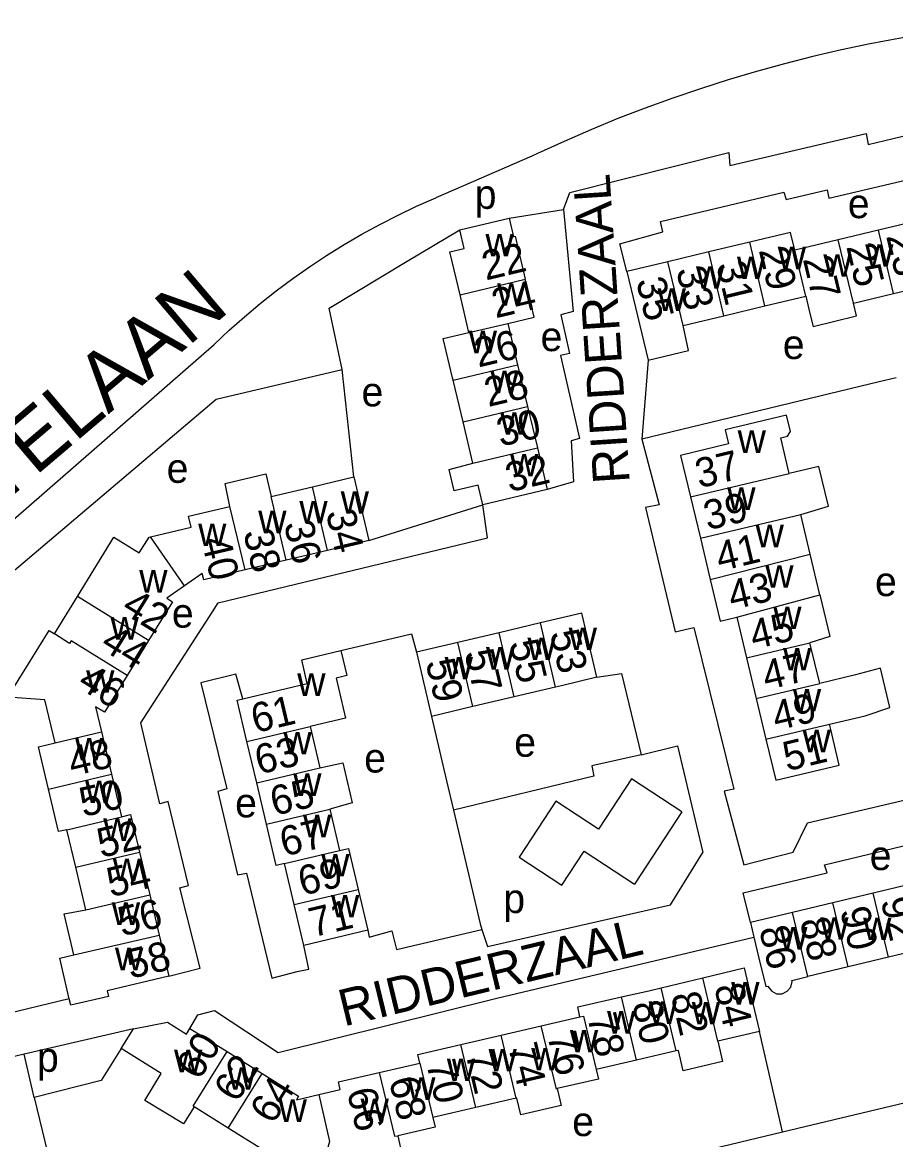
# Model space of a CAD drawing. Extents: x 157646 to 159241, y 379213 to 381217.
# Drawn here: x 158360.1 to 158479.3, y 380979.6 to 381132.2 of the extents above; entities that cross this region are included whole.
import ezdxf

# ---------------------------------------------------------------- set-up
doc = ezdxf.new("R2010")
doc.units = 0
for name, color, linetype in [('BLT_Basislijn', 7, 'Continuous'), ('BLT_Bebouwing', 7, 'Continuous'), ('BLT_Centroide', 7, 'Continuous'), ('BLT_Huisnummer', 7, 'Continuous'), ('BLT_Huisnummer_ tussenligend', 7, 'Continuous'), ('BLT_Onderverdeling_panden', 7, 'Continuous'), ('BLT_Straatnaam', 7, 'Continuous'), ('BLT_Straatnaam_hoofdweg', 7, 'Continuous')]:
    doc.layers.add(name, color=color, linetype=linetype)

msp = doc.modelspace()

# ---------------------------------------------------------------- linework, layer by layer
at = {"layer": 'BLT_Basislijn'}
for p, q in [((158429.63, 381113.93), (158416.55, 381108.25)), ((158352.16, 381058.47), (158386.26, 381088.22)), ((158445.52, 381086.08), (158444.65, 381075.27)), ((158405.32, 381070.12), (158403.73, 381084.79)), ((158477.05, 381083.1), (158444.65, 381075.27)), ((158479.4, 381083.66), (158477.05, 381083.1)), ((158407.38, 381061.43), (158422.93, 381066.31)), ((158415.95, 381037.42), (158418, 381028.6)), ((158418, 381028.6), (158418.93, 381024.62)), ((158443.27, 381028.88), (158438.76, 381022.01)), ((158450.14, 381024.37), (158443.27, 381028.88)), ((158432.92, 381025.85), (158427.89, 381018.19)), ((158438.76, 381022.01), (158432.92, 381025.85)), ((158418.93, 381024.62), (158422.56, 381009.1)), ((158450.14, 381024.37), (158443.66, 381014.5)), ((158433.74, 381014.35), (158436.79, 381019.01)), ((158436.79, 381019.01), (158443.66, 381014.5)), ((158427.89, 381018.19), (158433.74, 381014.35)), ((158422.56, 381009.1), (158422.81, 381008.33)), ((158424.88, 380998.94), (158459.96, 381007.29)), ((158366.47, 380998.84), (158355.18, 380996.12)), ((158375.23, 380994.76), (158360.32, 380991.27)), ((158463.89, 380980.68), (158460.71, 380994.38)), ((158463.89, 380980.68), (158511.15, 380991.95)), ((158360.32, 380991.27), (158351.84, 380989.29)), ((158361.67, 380985.35), (158360.32, 380991.27)), ((158418.22, 380969.78), (158463.89, 380980.68))]:
    msp.add_line(p, q, dxfattribs=at)
for points in [[(158495.56, 381132.22), (158491.59, 381131.78), (158487.63, 381131.27), (158483.68, 381130.68), (158479.74, 381130.02), (158475.82, 381129.27), (158471.91, 381128.44), (158468.02, 381127.54), (158464.15, 381126.56), (158460.3, 381125.5), (158456.47, 381124.36), (158452.66, 381123.15), (158448.88, 381121.86), (158445.13, 381120.5), (158441.4, 381119.06), (158437.71, 381117.55), (158434.04, 381115.96), (158430.41, 381114.3), (158429.63, 381113.93)], [(158433.98, 381106.64), (158434.82, 381108.99), (158456.55, 381114.43), (158456.67, 381112.68), (158475.29, 381117.04), (158475.59, 381115.54), (158485.82, 381118), (158484.86, 381122.23), (158495.46, 381124.81), (158496.3, 381121.35), (158503.33, 381123.36)], [(158442.63, 381098.18), (158441.67, 381101.95), (158447.51, 381103.59), (158447.19, 381105.03), (158464.06, 381109.04), (158464.35, 381108.01), (158469.95, 381109.35), (158470.21, 381108.19), (158480.86, 381110.72), (158480.68, 381111.49), (158492.02, 381114.24), (158492.32, 381112.97), (158498.99, 381114.49), (158499.82, 381110.23), (158498.96, 381110.26)], [(158386.26, 381088.22), (158388.3, 381090.15), (158390.39, 381092.01), (158392.54, 381093.81), (158394.74, 381095.55), (158396.98, 381097.23), (158399.27, 381098.84), (158401.61, 381100.39), (158403.99, 381101.87), (158406.41, 381103.28), (158408.87, 381104.62), (158411.37, 381105.89), (158413.9, 381107.09), (158416.55, 381108.25)], [(158426.53, 381105.47), (158433.98, 381106.64)], [(158433.98, 381106.64), (158435.27, 381092.73), (158433.61, 381092.25), (158434.78, 381086.99), (158433.57, 381086.7), (158436.16, 381075.36), (158434.99, 381075.07), (158435.31, 381069.47), (158431.73, 381068.4)], [(158403.73, 381084.79), (158401.98, 381093.18), (158412.6, 381099.61), (158419.79, 381103.88)], [(158346.67, 381046.99), (158386.52, 381080.76), (158403.73, 381084.79)], [(158444.65, 381075.27), (158447.01, 381066.3), (158445.18, 381065.93), (158449.2, 381048.97), (158451.75, 381049.54), (158457.24, 381027.49), (158455.91, 381027.23), (158458.57, 381017.13), (158465.31, 381018.9)], [(158382.77, 381014.34), (158379.96, 381025.82), (158378.84, 381025.49), (158376.22, 381036.56), (158386.05, 381051.68), (158386.8, 381052.92), (158423.59, 381061.81), (158422.93, 381066.31)], [(158403.56, 381046.4), (158413.19, 381048.68)], [(158413.19, 381048.68), (158413.87, 381046.18)], [(158438.53, 381042.77), (158441.86, 381043.28), (158444.57, 381032.17)], [(158390.15, 381039.84), (158389.23, 381043.18), (158384.44, 381042.01), (158387.97, 381027.53), (158386.77, 381027.16), (158389.44, 381015.77)], [(158444.57, 381032.17), (158449.51, 381033.41), (158452.97, 381018.84)], [(158444.57, 381032.17), (158437.82, 381030.67), (158438.09, 381029.27), (158418.93, 381024.62)], [(158465.31, 381018.9), (158467.28, 381022.88), (158492.26, 381028.74)], [(158459.49, 381009.28), (158458.48, 381013.34), (158469.96, 381016.06), (158469.6, 381017.14), (158492.15, 381022.55), (158492.37, 381021.36), (158503.42, 381023.91), (158504.71, 381018.63)], [(158422.81, 381008.33), (158423.59, 381005.98), (158448.59, 381011.68), (158452.97, 381018.84)], [(158389.44, 381015.77), (158390.66, 381016.02), (158394.12, 381001.66), (158397.6, 381002.57), (158399.19, 381002.91), (158398.51, 381006.15)], [(158380.07, 381001.96), (158384.33, 381003.02), (158381.55, 381013.99), (158382.77, 381014.34)], [(158407.22, 381008.21), (158407.43, 381007.29), (158410.51, 381008.13), (158411.15, 381005.59), (158422.81, 381008.33)], [(158382.95, 380994.79), (158384.04, 380996.64), (158386.3, 380997.24), (158395, 380991.53), (158424.88, 380998.94)], [(158373.55, 380992.07), (158370.81, 380987.7), (158361.67, 380985.35)], [(158361.67, 380985.35), (158363.86, 380976.35), (158369.39, 380964.25)]]:
    msp.add_lwpolyline(points, dxfattribs=at)
at = {"layer": 'BLT_Bebouwing'}
for p, q in [((158419.79, 381103.88), (158426.53, 381105.47)), ((158482.7, 381105.19), (158476.98, 381103.83)), ((158476.98, 381103.83), (158471.48, 381102.52)), ((158459.39, 381102.18), (158453.8, 381100.85)), ((158471.48, 381102.52), (158465.55, 381101.1)), ((158453.8, 381100.85), (158448.21, 381099.52)), ((158448.21, 381099.52), (158442.63, 381098.18)), ((158442.63, 381098.18), (158445.52, 381086.08)), ((158473.55, 381093.88), (158479.05, 381095.2)), ((158421.05, 381089.85), (158419.83, 381095.02)), ((158461.47, 381093.49), (158467.05, 381094.82)), ((158450.29, 381090.82), (158455.88, 381092.15)), ((158455.88, 381092.15), (158461.47, 381093.49)), ((158426.36, 381091.1), (158427.7, 381085.43)), ((158427.7, 381085.43), (158429.05, 381079.75)), ((158420.24, 381077.67), (158418.9, 381083.34)), ((158429.05, 381079.75), (158430.39, 381074.08)), ((158421.59, 381071.99), (158420.24, 381077.67)), ((158430.39, 381074.08), (158431.73, 381068.4)), ((158399.68, 381068.78), (158405.32, 381070.12)), ((158405.32, 381070.12), (158407.38, 381061.43)), ((158394.05, 381067.45), (158399.68, 381068.78)), ((158431.73, 381068.4), (158422.93, 381066.31)), ((158451.3, 381067.41), (158452.65, 381061.76)), ((158467.67, 381059.56), (158466.38, 381064.99)), ((158377.57, 381061.94), (158383.13, 381063.26)), ((158452.65, 381061.76), (158454, 381056.1)), ((158401.74, 381060.09), (158396.11, 381058.76)), ((158407.38, 381061.43), (158401.74, 381060.09)), ((158396.11, 381058.76), (158390.47, 381057.42)), ((158468.99, 381054.03), (158467.67, 381059.56)), ((158384.63, 381056.95), (158382.2, 381055.26)), ((158382.2, 381055.26), (158379.78, 381053.58)), ((158364.45, 381048.72), (158367.57, 381053.78)), ((158457.62, 381050.99), (158458.95, 381045.42)), ((158430.81, 381050.19), (158425.17, 381048.85)), ((158425.17, 381048.85), (158419.52, 381047.51)), ((158377.31, 381047.78), (158374.37, 381043.02)), ((158419.52, 381047.51), (158413.87, 381046.18)), ((158468.95, 381041.92), (158467.62, 381047.49)), ((158458.95, 381045.42), (158460.28, 381039.86)), ((158374.37, 381043.02), (158371.27, 381037.98)), ((158432.89, 381041.43), (158427.24, 381040.09)), ((158371.27, 381037.98), (158370.07, 381038.72)), ((158370.07, 381038.72), (158370.88, 381035.31)), ((158389.39, 381039.66), (158390.15, 381039.84)), ((158390.73, 381034.01), (158389.39, 381039.66)), ((158421.59, 381038.75), (158415.95, 381037.42)), ((158427.24, 381040.09), (158421.59, 381038.75)), ((158460.28, 381039.86), (158461.61, 381034.29)), ((158399.36, 381036.05), (158400.7, 381030.4)), ((158370.88, 381035.31), (158372.25, 381029.52)), ((158461.61, 381034.29), (158462.94, 381028.72)), ((158392.07, 381028.36), (158390.73, 381034.01)), ((158372.25, 381029.52), (158373.62, 381023.72)), ((158462.94, 381028.72), (158471.61, 381030.78)), ((158393.41, 381022.71), (158392.07, 381028.36)), ((158402.04, 381024.75), (158403.38, 381019.1)), ((158367.36, 381016.82), (158366.15, 381021.95)), ((158376.06, 381018.89), (158377.45, 381013.04)), ((158397.19, 381011.73), (158395.87, 381017.32)), ((158368.74, 381010.98), (158367.36, 381016.82)), ((158481.75, 381014.6), (158476.26, 381013.29)), ((158377.45, 381013.04), (158378.74, 381007.56)), ((158405.9, 381013.8), (158407.22, 381008.21)), ((158476.26, 381013.29), (158470.74, 381011.97)), ((158398.51, 381006.15), (158397.19, 381011.73)), ((158470.74, 381011.97), (158465.23, 381010.65)), ((158465.23, 381010.65), (158459.49, 381009.28)), ((158407.22, 381008.21), (158398.51, 381006.15)), ((158459.49, 381009.28), (158459.96, 381007.29)), ((158378.74, 381007.56), (158380.07, 381001.96)), ((158453, 381001.72), (158458.64, 381003.07)), ((158472.84, 381003.2), (158467.33, 381001.89)), ((158447.32, 381000.37), (158453, 381001.72)), ((158430.93, 380995.16), (158436.21, 380996.39)), ((158373.55, 380992.07), (158375.23, 380994.76)), ((158375.23, 380994.76), (158379.89, 380995.64)), ((158379.89, 380995.64), (158382.48, 380994.03)), ((158382.48, 380994.03), (158382.95, 380994.79)), ((158382.95, 380994.79), (158388.01, 380991.64)), ((158425.45, 380993.89), (158430.93, 380995.16)), ((158419.96, 380992.61), (158425.45, 380993.89)), ((158460.71, 380994.38), (158455.02, 380993.05)), ((158379.02, 380988.67), (158373.55, 380992.07)), ((158388.01, 380991.64), (158392.81, 380988.65)), ((158449.33, 380991.73), (158443.92, 380990.47)), ((158408.8, 380988.78), (158414.35, 380990.07)), ((158443.92, 380990.47), (158438.42, 380989.19)), ((158397.48, 380985.06), (158400.54, 380985.78)), ((158400.54, 380985.78), (158403.48, 380986.46)), ((158427.48, 380985.27), (158421.99, 380983.99)), ((158388.17, 380981.2), (158383.52, 380984.09)), ((158421.99, 380983.99), (158416.12, 380982.62)), ((158393.14, 380978.1), (158388.17, 380981.2))]:
    msp.add_line(p, q, dxfattribs=at)
for points in [[(158426.53, 381105.47), (158427.13, 381102.93), (158427.36, 381102.99), (158428.74, 381097.13)], [(158419.83, 381095.02), (158418.44, 381100.88), (158420.39, 381101.34), (158419.79, 381103.88)], [(158465.55, 381101.1), (158464.98, 381103.52), (158459.39, 381102.18)], [(158426.36, 381091.1), (158429.97, 381091.96), (158428.74, 381097.13)], [(158479.05, 381095.2), (158484.76, 381096.56), (158484.49, 381097.68)], [(158467.05, 381094.82), (158467.62, 381092.47), (158468.04, 381090.69), (158473.97, 381092.11), (158473.55, 381093.88)], [(158445.52, 381086.08), (158451.01, 381087.39), (158450.29, 381090.82)], [(158418.9, 381083.34), (158418.82, 381083.68), (158417.55, 381089.02), (158421.05, 381089.85)], [(158464.8, 381070.59), (158463.64, 381075.46), (158464.53, 381075.68), (158464.97, 381076.32), (158464.43, 381078.58), (158456.04, 381076.58), (158456.51, 381074.63), (158449.95, 381073.06), (158451.3, 381067.41)], [(158422.93, 381066.31), (158422.3, 381068.98), (158419.02, 381068.21), (158418.33, 381071.16), (158421.59, 381071.99)], [(158466.38, 381064.99), (158470.14, 381066.14), (158468.84, 381071.55), (158464.8, 381070.59)], [(158388.41, 381066.11), (158387.77, 381069.23), (158393.31, 381070.54), (158394.05, 381067.45)], [(158383.13, 381063.26), (158382.77, 381064.78), (158388.41, 381066.11)], [(158367.57, 381053.78), (158372.57, 381061.88), (158376.03, 381059.74)], [(158376.03, 381059.74), (158377.36, 381061.89), (158377.57, 381061.94)], [(158390.47, 381057.42), (158384.83, 381056.09), (158384.63, 381056.95)], [(158454, 381056.1), (158455.35, 381050.45), (158457.62, 381050.99)], [(158468.99, 381054.03), (158470.35, 381048.34), (158467.62, 381047.49)], [(158379.78, 381053.58), (158380.58, 381053.08), (158377.31, 381047.78)], [(158438.53, 381042.77), (158436.46, 381051.52), (158430.81, 381050.19)], [(158358.07, 381040.03), (158363.71, 381049.17), (158364.45, 381048.72)], [(158390.15, 381039.84), (158398.97, 381041.92), (158398.21, 381045.14), (158403.56, 381046.4)], [(158403.56, 381046.4), (158404.37, 381043), (158402.91, 381042.65), (158404.2, 381037.2), (158399.36, 381036.05)], [(158413.87, 381046.18), (158415.02, 381041.31), (158415.95, 381037.42)], [(158470.28, 381036.35), (158475.15, 381037.5), (158478.53, 381038.65), (158477.25, 381044.02), (158473.82, 381043.09), (158468.95, 381041.92)], [(158438.53, 381042.77), (158433.67, 381041.61), (158432.89, 381041.43)], [(158364.54, 381033.81), (158363.15, 381039.7), (158358.07, 381040.03)], [(158471.61, 381030.78), (158470.45, 381035.65), (158470.28, 381036.35)], [(158363.65, 381027.48), (158362.27, 381033.28), (158364.54, 381033.81)], [(158400.7, 381030.4), (158403.84, 381031.06), (158405.12, 381025.63), (158402.04, 381024.75)], [(158366.15, 381021.95), (158365.02, 381021.68), (158363.65, 381027.48)], [(158373.62, 381023.72), (158374.85, 381024.01), (158376.06, 381018.89)], [(158395.87, 381017.32), (158394.74, 381017.06), (158393.41, 381022.71)], [(158403.38, 381019.1), (158404.58, 381019.39), (158405.9, 381013.8)], [(158367.08, 381004.86), (158365.76, 381010.44), (158368.74, 381010.98)], [(158459.96, 381007.29), (158460.65, 381004.42), (158461.58, 381000.52), (158461.89, 381000.59), (158461.91, 381000.48), (158462.39, 380999.88), (158463.07, 380999.54), (158463.84, 380999.54), (158464.52, 380999.87), (158465, 381000.46), (158465.18, 381001.21), (158465.14, 381001.37), (158467.33, 381001.89)], [(158484.06, 381005.88), (158478.36, 381004.52)], [(158366.47, 380998.84), (158365.16, 381004.4), (158367.08, 381004.86)], [(158478.36, 381004.52), (158472.84, 381003.2)], [(158458.64, 381003.07), (158459.37, 381000), (158459.8, 380998.21), (158460.71, 380994.38)], [(158380.07, 381001.96), (158371.65, 380999.96), (158371.84, 380999.18), (158366.68, 380997.96), (158366.47, 380998.84)], [(158436.21, 380996.39), (158435.9, 380997.74), (158441.86, 380999.13)], [(158441.86, 380999.13), (158445.62, 380999.96), (158445.78, 381000), (158447.32, 381000.37)], [(158455.02, 380993.05), (158455.66, 380990.28), (158450.29, 380989.03), (158449.65, 380991.8), (158449.33, 380991.73)], [(158414.35, 380990.07), (158414.08, 380991.24), (158419.96, 380992.61)], [(158383.52, 380984.09), (158382.07, 380981.76), (158376.77, 380984.95), (158379.02, 380988.67)], [(158392.81, 380988.65), (158397.78, 380985.55), (158397.48, 380985.06)], [(158403.48, 380986.46), (158403.24, 380987.49), (158408.8, 380988.78)], [(158438.42, 380989.19), (158438.72, 380987.88), (158433.11, 380986.58)], [(158433.11, 380986.58), (158433.65, 380984.28), (158428.14, 380983), (158427.6, 380985.29), (158427.48, 380985.27)], [(158416.12, 380982.62), (158416.43, 380981.31), (158411.32, 380980.12)], [(158411.32, 380980.12), (158411.94, 380977.42), (158405.94, 380976.02), (158405.64, 380977.32)]]:
    msp.add_lwpolyline(points, dxfattribs=at)
at = {"layer": 'BLT_Onderverdeling_panden'}
for p, q in [((158479.05, 381095.2), (158476.98, 381103.83)), ((158461.47, 381093.49), (158459.39, 381102.18)), ((158473.55, 381093.88), (158471.48, 381102.52)), ((158455.88, 381092.15), (158453.8, 381100.85)), ((158467.05, 381094.82), (158465.55, 381101.1)), ((158450.29, 381090.82), (158448.21, 381099.52)), ((158419.83, 381095.02), (158428.74, 381097.13)), ((158421.05, 381089.85), (158426.36, 381091.1)), ((158418.9, 381083.34), (158427.7, 381085.43)), ((158420.24, 381077.67), (158429.05, 381079.75)), ((158421.59, 381071.99), (158430.39, 381074.08)), ((158451.3, 381067.41), (158464.8, 381070.59)), ((158401.74, 381060.09), (158399.68, 381068.78)), ((158396.11, 381058.76), (158394.05, 381067.45)), ((158390.47, 381057.42), (158388.41, 381066.11)), ((158452.65, 381061.76), (158466.38, 381064.99)), ((158382.2, 381055.26), (158377.57, 381061.94)), ((158454, 381056.1), (158467.67, 381059.56)), ((158457.62, 381050.99), (158468.99, 381054.03)), ((158377.31, 381047.78), (158367.57, 381053.78)), ((158432.89, 381041.43), (158430.81, 381050.19)), ((158427.24, 381040.09), (158425.17, 381048.85)), ((158421.59, 381038.75), (158419.52, 381047.51)), ((158458.95, 381045.42), (158467.62, 381047.49)), ((158460.28, 381039.86), (158468.95, 381041.92)), ((158390.73, 381034.01), (158399.36, 381036.05)), ((158461.61, 381034.29), (158470.28, 381036.35)), ((158364.54, 381033.81), (158370.88, 381035.31)), ((158363.65, 381027.48), (158372.25, 381029.52)), ((158392.07, 381028.36), (158400.7, 381030.4)), ((158366.15, 381021.95), (158373.62, 381023.72)), ((158393.41, 381022.71), (158402.04, 381024.75)), ((158367.36, 381016.82), (158376.06, 381018.89)), ((158395.87, 381017.32), (158403.38, 381019.1)), ((158368.74, 381010.98), (158377.45, 381013.04)), ((158397.19, 381011.73), (158405.9, 381013.8)), ((158478.36, 381004.52), (158476.26, 381013.29)), ((158472.84, 381003.2), (158470.74, 381011.97)), ((158467.33, 381001.89), (158465.23, 381010.65)), ((158367.08, 381004.86), (158378.74, 381007.56)), ((158455.02, 380993.05), (158453, 381001.72)), ((158443.92, 380990.47), (158441.86, 380999.13)), ((158449.33, 380991.73), (158447.32, 381000.37)), ((158427.48, 380985.27), (158425.45, 380993.89)), ((158421.99, 380983.99), (158419.96, 380992.61)), ((158414.35, 380990.07), (158416.12, 380982.62)), ((158388.17, 380981.2), (158392.81, 380988.65))]:
    msp.add_line(p, q, dxfattribs=at)
for points in [[(158374.37, 381043.02), (158366.72, 381047.74), (158366.5, 381047.38), (158364.45, 381048.72)], [(158436.21, 380996.39), (158436.69, 380996.48), (158438.42, 380989.19)], [(158433.11, 380986.58), (158432.99, 380986.51), (158430.93, 380995.16)], [(158383.52, 380984.09), (158383.37, 380984.19), (158388.01, 380991.64)], [(158408.8, 380988.78), (158410.87, 380980.09), (158411.32, 380980.12)], [(158400.54, 380985.78), (158402.02, 380979.35), (158401.16, 380976.28)]]:
    msp.add_lwpolyline(points, dxfattribs=at)

# ---------------------------------------------------------------- texts
at = {"layer": 'BLT_Centroide'}
for s, p in [('p', (158421.84, 381106.74)), ('e', (158472.79, 381105.47)), ('w', (158423.3, 381100.25)), ('w', (158463.22, 381098.5)), ('w', (158475.16, 381098.84)), ('w', (158457.64, 381097.16)), ('w', (158469.44, 381097.47)), ('w', (158452.05, 381095.84)), ('w', (158424.9, 381093.5)), ('w', (158446.81, 381092.8)), ('w', (158421.02, 381087.03)), ('e', (158430.83, 381087.31)), ('e', (158463.91, 381086.23)), ('w', (158423.98, 381081.56)), ('e', (158406.38, 381079.76)), ('w', (158425.32, 381075.88)), ('w', (158457.74, 381073.41)), ('e', (158379.77, 381069.32)), ('w', (158426.66, 381070.19)), ('w', (158403.53, 381065.11)), ('w', (158456.32, 381065.62)), ('w', (158397.89, 381063.78)), ('w', (158392.27, 381062.44)), ('w', (158384.07, 381060.69)), ('w', (158460.19, 381060.53)), ('w', (158376.02, 381054.33)), ('w', (158461.52, 381055)), ('e', (158476.5, 381053.85)), ('e', (158380.48, 381049.54)), ('w', (158462.6, 381049.34)), ('w', (158372.09, 381047.91)), ('w', (158434.67, 381046.47)), ('w', (158429.03, 381045.12)), ('w', (158423.38, 381043.81)), ('w', (158463.95, 381043.69)), ('w', (158417.73, 381042.47)), ('w', (158368.77, 381040.64)), ('w', (158397.6, 381040.22)), ('w', (158465.28, 381038.09)), ('w', (158367.26, 381031.41)), ('w', (158395.71, 381032.22)), ('e', (158427.23, 381031.91)), ('w', (158466.61, 381032.53)), ('e', (158406.74, 381029.75)), ('w', (158397.05, 381026.56)), ('w', (158368.63, 381025.59)), ('e', (158389.12, 381023.63)), ('w', (158371.11, 381020.41)), ('w', (158398.39, 381020.91)), ('e', (158475.78, 381016.43)), ('w', (158372.41, 381014.94)), ('w', (158400.88, 381015.56)), ('w', (158402.21, 381009.97)), ('p', (158425.74, 381010.56)), ('w', (158372.27, 381008.94)), ('w', (158469.03, 381006.92)), ('w', (158474.88, 381006.86)), ('w', (158463.41, 381005.58)), ('w', (158372.71, 381002.75)), ('w', (158456.86, 380998.06)), ('w', (158445.59, 380995.42)), ('w', (158451.48, 380995.34)), ('w', (158439.91, 380994.11)), ('w', (158434.83, 380991.52)), ('p', (158362.06, 380988.88)), ('w', (158380.78, 380988.81)), ('w', (158423.72, 380988.94)), ('w', (158429.55, 380989.08)), ('w', (158418.03, 380987.61)), ('w', (158388.09, 380986.42)), ('w', (158412.61, 380985.05)), ('w', (158395.05, 380982.03)), ('w', (158406.25, 380982.14)), ('e', (158435.15, 380980.1))]:
    msp.add_text(s, height=4, dxfattribs=at).set_placement(p)
at = {"layer": 'BLT_Huisnummer'}
for s, rotation, p in [('22', 13.3253, (158423.35, 381096.95)), ('29', 283.423, (158460.61, 381101.1)), ('25', 283.423, (158472.56, 381101.6)), ('35', 283.423, (158443.86, 381096.94)), ('28', 13.325, (158423.68, 381079.67)), ('37', 13.4222, (158452.49, 381068.57)), ('32', 13.3236, (158426.57, 381068.03)), ('34', 283.3283, (158401.49, 381065.27)), ('40', 283.3851, (158384.48, 381061.49)), ('41', 13.4222, (158455.3, 381057.21)), ('42', 328.3223, (158373.41, 381051.72)), ('45', 13.4222, (158459.94, 381046.54)), ('53', 283.3214, (158432.07, 381048.81)), ('59', 283.3176, (158415.11, 381044.84)), ('46', 328.3231, (158367.4, 381041.48)), ('61', 13.3263, (158391.84, 381035.12)), ('48', 13.3306, (158366.86, 381029.21)), ('51', 13.4222, (158464.46, 381029.92)), ('65', 13.3263, (158394.45, 381023.82)), ('52', 13.3306, (158370.8, 381018.08)), ('71', 13.3237, (158399.72, 381007.24)), ('90', 283.3272, (158471.71, 381010.96)), ('86', 283.3272, (158460.65, 381008.38)), ('58', 13.3275, (158374.81, 381001.57)), ('84', 283.3272, (158454.52, 381000.5)), ('78', 283.3272, (158437.18, 380996.41)), ('60', 58.1012, (158384.2, 380987.57)), ('74', 283.3272, (158426.37, 380992.34)), ('70', 283.3272, (158415.2, 380990.04)), ('64', 58.0516, (158394.29, 380981.56)), ('66', 283.3272, (158404.36, 380986.25))]:
    msp.add_text(s, height=4, rotation=rotation, dxfattribs=at).set_placement(p)
at = {"layer": 'BLT_Huisnummer_ tussenligend'}
for s, rotation, p in [('23', 283.423, (158478, 381103.04)), ('27', 283.423, (158466.63, 381099.89)), ('33', 283.423, (158449.33, 381098.42)), ('31', 283.423, (158454.79, 381099.13)), ('24', 13.3253, (158424.69, 381091.78)), ('26', 13.325, (158422.32, 381085.06)), ('30', 13.325, (158425.36, 381074.24)), ('39', 13.4222, (158453.64, 381062.83)), ('36', 283.3283, (158395.76, 381063.73)), ('38', 283.3283, (158390.21, 381062.58)), ('43', 13.4222, (158456.97, 381051.94)), ('44', 328.3223, (158370.53, 381046.76)), ('55', 283.3214, (158426.53, 381047.47)), ('57', 283.3214, (158420.4, 381046.14)), ('47', 13.4222, (158461.65, 381040.99)), ('49', 13.4222, (158463, 381035.44)), ('63', 13.3263, (158392.36, 381029.47)), ('50', 13.3306, (158368.38, 381023.66)), ('67', 13.3263, (158395.77, 381018.27)), ('54', 13.3306, (158372.12, 381012.71)), ('69', 13.3263, (158398.27, 381012.91)), ('92', 283.3272, (158477.26, 381012.28)), ('56', 13.3306, (158373.65, 381007.36)), ('88', 283.3272, (158466.2, 381009.52)), ('82', 283.3272, (158448.59, 380999.34)), ('80', 283.3272, (158443.3, 380998.14)), ('76', 283.3272, (158431.72, 380993.87)), ('72', 283.3272, (158420.56, 380991.37)), ('62', 58.1012, (158389.37, 380984.52)), ('68', 283.3272, (158410.1, 380987.77))]:
    msp.add_text(s, height=4, rotation=rotation, dxfattribs=at).set_placement(p)
at = {"layer": 'BLT_Straatnaam'}
for rotation, p in [(93.7576, (158443.02, 381069.36)), (13.5825, (158403.95, 380995.05))]:
    msp.add_text('RIDDERZAAL', height=5, rotation=rotation, dxfattribs=at).set_placement(p)
at = {"layer": 'BLT_Straatnaam_hoofdweg'}
msp.add_text('KAREL DE GROTELAAN', height=8, rotation=40.3442, dxfattribs=at).set_placement((158295.67, 381013.98))

doc.saveas('drawing.dxf')
